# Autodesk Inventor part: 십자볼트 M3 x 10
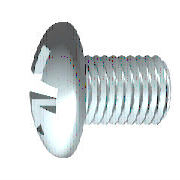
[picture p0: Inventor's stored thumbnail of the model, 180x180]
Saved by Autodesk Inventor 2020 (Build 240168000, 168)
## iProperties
Created: 2012-02
Part Number: 십자볼트 M3 x 10
Material: 스테인리스강
Description: 십자 오목 머리 나사
Document SubType Name: Modeling
Standard: KS B 1023
Designer: mduedu
Standards Organization: KS
Language: ko-KR
Size Designation: A  M 3 x 10 - H
Categories: <MemberInstance><Categories><Category DisplayName="조임쇠" InternalName="e4da775c-781d-43d5-af7c-5136215cf5a6" Mnemonic="FSTN"><Category DisplayName="볼트" InternalN
Density: 1 g/cm^3
Appearance: 반광택
IsCustomPart: 0
Author: mduedu
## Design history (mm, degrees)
workplane "Work Plane3"
body "Solid1"
sketch "스케치2"
  geometry: L1 (-3.72, 0)-(3.72, 0) reference; L2 (0, -3.72)-(0, 3.72) reference; L3 (0, 1.5)-(0, 0); L4 (0, 0)-(1.5, 0); L5 (0, 0)-(1.879, 1.879); L6 (0.253, 1.479)-(0.261, 0.456); L7 (1.479, 0.253)-(0.456, 0.261); L8 (0.253, -1.479)-(0.261, -0.456); L9 (1.479, -0.253)-(0.456, -0.261); L10 (-0.253, 1.479)-(-0.261, 0.456); L11 (-1.479, 0.253)-(-0.456, 0.261); L12 (-1.479, -0.253)-(-0.456, -0.261); L13 (-0.253, -1.479)-(-0.261, -0.456); A1 r 0.45 centre (0, 0) between (0.45, 0) and (0, 0.45); A2 r 1.5 centre (0, 0) between (1.5, 0) and (1.479, 0.253); A3 r 1.5 centre (0, 0) between (0.253, 1.479) and (0, 1.5); A4 r 1.5 centre (0, 0) between (1.479, 0.253) and (0.253, 1.479); A5 r 1.5 centre (0, 0) between (0, -1.5) and (0.253, -1.479); A6 r 1.5 centre (0, 0) between (0.253, -1.479) and (1.479, -0.253); A7 r 1.5 centre (0, 0) between (1.479, -0.253) and (1.5, 0); A8 r 1.5 centre (0, 0) between (-1.479, 0.253) and (-1.5, 0); A9 r 1.5 centre (0, 0) between (-0.253, 1.479) and (-1.479, 0.253); A10 r 1.5 centre (0, 0) between (0, 1.5) and (-0.253, 1.479); A11 r 1.5 centre (0, 0) between (-1.5, 0) and (-1.479, -0.253); A12 r 1.5 centre (0, 0) between (-1.479, -0.253) and (-0.253, -1.479); A13 r 1.5 centre (0, 0) between (-0.253, -1.479) and (0, -1.5); A14 r 0.525 centre (0, 0) between (0.525, 0) and (0, 0.525); A15 r 0.197 centre (0.457, 0.457) between (0.261, 0.456) and (0.456, 0.261); A16 r 0.197 centre (0.457, -0.457) between (0.456, -0.261) and (0.261, -0.456); A17 r 0.197 centre (-0.457, 0.457) between (-0.456, 0.261) and (-0.261, 0.456); A18 r 0.197 centre (-0.457, -0.457) between (-0.261, -0.456) and (-0.456, -0.261); 1 further point
  constraints: 38 point on circle, 22 end point, 19 symmetric about line, 18 centre point, 4 coincident, 3 collinear, 3 point on line, 3 tangent, 1 perpendicular, 21 other
  dimensions: "d4" = 45 deg angle of L5 L4; "d5" = 0.9 diameter of A1 (= 0.3 x SDM); "d6" = 3 diameter of A4 (= SDM); "d7" = 0.2525 distance from line of L6.start L3 (= 0.5 x SBR); "d14" = 1.05 diameter of A14 (= 0.35 x SDM)
extrude "슬롯" join sketch "스케치2" taper "d15" = 5 deg; stored distance "d54" = 10
revolve "절단부" stored, may be unused: angle "d56" = 90 deg
revolve "본체" stored, may be unused: angle "d18" = 90 deg
workplane "Work Plane1"
sketch "스케치1"
  geometry: L1 (10, 0)-(10, 1.5); L2 (10, 1.5)-(1, 1.5); L3 (3.962, 5.08)-(3.962, 5.08); L4 (-2.4, 0)-(-2.4, 2.59); L5 (-2.2, 1.4)-(-1.036, 0.82); L6 (-1.036, 0.82)-(-0.6, 0); L7 (-0.6, 0)-(10, 0); L8 (-5.105, 0)-(12.517, 0) reference; L9 (0, -1.016)-(0, 6.096) reference; L10 (-2.2, 1.4)-(-2.4, 1.5); L11 (-1.636, 2.657)-(-2.4, 2.59); L12 (-1.636, 2.657)-(0, 2.8); L13 (0, 2.8)-(0, 1.347); L14 (0, 1.347)-(0.693, 1.347); L15 (0.693, 1.347)-(1, 1.5); L16 (1, 1.5)-(0, 1.5); A1 r 5 centre (2.6, 0) between (-1.636, 2.657) and (-2.4, 0)
  constraints: 28 end point, 5 point on line, 4 collinear, 4 point on circle, 3 parallel, 2 perpendicular, 1 centre point, 1 horizontal, 1 tangent
  dimensions: "d1" = 3 diameter of L2 L7 (= GD); "d2" = 1.8 distance from line of L6.end L4 (= STI); "d11" = 3 diameter of L10.end L7 (= SDM); "d12" = 62 deg angle of L6 L7; "d13" = 26.5 deg angle of L5 L7; "d17" = 5.6 diameter of L12.end L7 (= KOD); "d19" = 5 deg angle of L12 L7 (= KEWI); "d20" = 2.4 distance between parallel lines of L4 L13 (= KOH); "d21" = 5 radius of A1 (= KR); "d23" = 2.6935 diameter of L14 L7 (= BDM); "d24" = 9 distance of L1.end L2.end (= GEL); "d25" = 0.30673 horizontal distance of L14.end L2.end (= GAL); "d28" = 10 distance between parallel lines of L1 L13 (= NLG)
fillet "모깎기1" dims "d29" = 1.2 (= RR)
fillet "모깎기2" dims "d16" = 0.101 (= 0.2 x SBR)
feature "스레드" dims "d8" = 9 (= GEL), "d9" = 0
chamfer "모따기1" distance "d26" = 0.30673 (= -0.5 x SPD + 0.5 x GD); stored, may be unused: second distance "d27" = 0.30683 (computed from GUL), angle "d78" = 45 deg
other parameters: "GD" = 3 (= NND) [user parameter; used in 2 equation terms], "NLG" = 10 [user parameter; used in 1 equation term], "GEL" = 9 [user parameter; used in 2 equation terms], "KOD" = 5.6 [user parameter; used in 1 equation term], "KOH" = 2.4 [user parameter; used in 2 equation terms], "SDM" = 3 [user parameter; used in 4 equation terms], "STI" = 1.8 [user parameter; used in 1 equation term], "SBR" = 0.505 [user parameter; used in 2 equation terms], "GAL" = 0.30673 (= 0.61345 x PTC) [user parameter; used in 1 equation term], "SPD" = 2.38655 (= NND - 1.2269 x PTC) [user parameter; used in 1 equation term], "KEWI" = 5 deg [user parameter; used in 1 equation term], "d3" = -2.4 (= -KOH), "d10" = 0, "KR" = 5 [user parameter; used in 1 equation term], "BDM" = 2.6935 [user parameter; used in 1 equation term], "GUL" = 0.30673 (= 0.61345 x PTC) [user parameter; used in 1 equation term], "RR" = 1.2 [user parameter; used in 1 equation term], "d79" = 0, "d80" = 0, "PTC" = 0.5 [user parameter; used in 5 equation terms], "THREADDIA" = 3 [user parameter; used in 1 equation term], "TOA" = 30 deg [user parameter], "NND" = 3 [user parameter; used in 2 equation terms], "GD1" = 2.38655 (= THREADDIA - 1.2269 x PTC) [user parameter]
